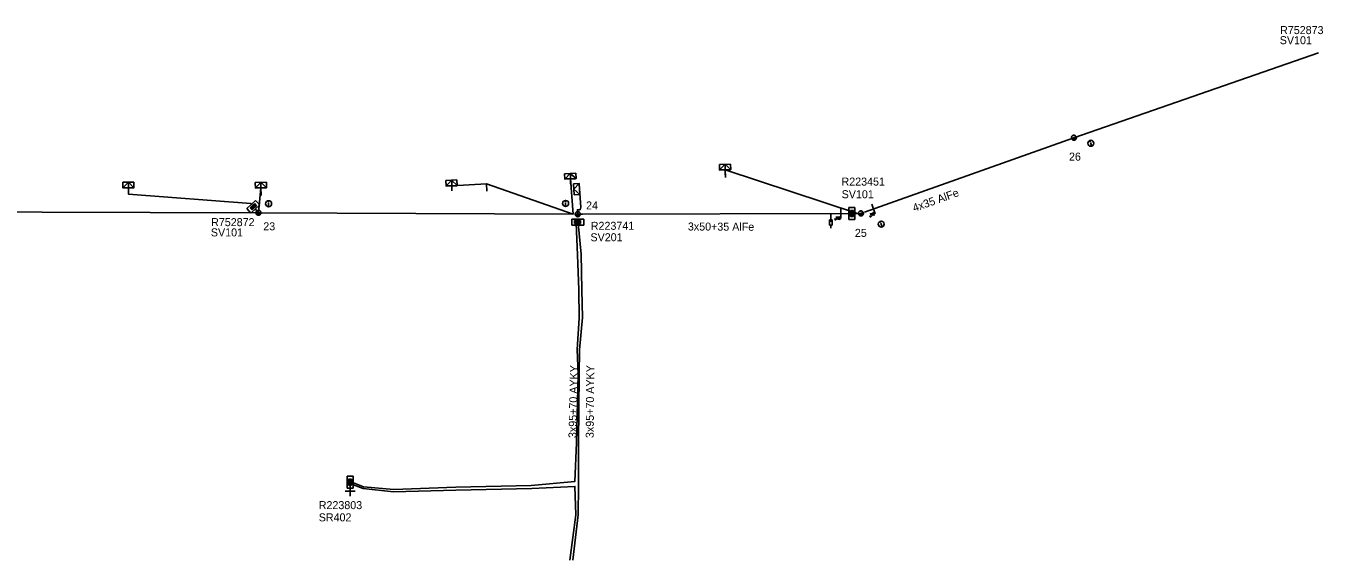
# Model space of a CAD drawing. Extents: x -544780 to -541582, y -1198995 to -1196551.
# Drawn here: x -541744 to -541581.9, y -1198987 to -1198920.2 of the extents above; entities that cross this region are included whole.
import ezdxf

# ---------------------------------------------------------------- set-up
doc = ezdxf.new("R2010")
doc.units = 0
for name, color, linetype in [('Vrstva 1', 7, 'Continuous'), ('Vrstva 10', 7, 'Continuous'), ('Vrstva 13', 7, 'Continuous'), ('Vrstva 14', 7, 'Continuous'), ('Vrstva 15', 7, 'Continuous'), ('Vrstva 16', 7, 'Continuous'), ('Vrstva 18', 7, 'Continuous'), ('Vrstva 2', 7, 'Continuous'), ('Vrstva 28', 7, 'Continuous'), ('Vrstva 29', 7, 'Continuous'), ('Vrstva 30', 7, 'Continuous'), ('Vrstva 31', 7, 'Continuous'), ('Vrstva 34', 7, 'Continuous'), ('Vrstva 36', 7, 'Continuous'), ('Vrstva 5', 7, 'Continuous'), ('Vrstva 52', 7, 'Continuous'), ('Vrstva 54', 7, 'Continuous'), ('Vrstva 59', 7, 'Continuous'), ('Vrstva 6', 7, 'Continuous'), ('Vrstva 8', 7, 'Continuous'), ('Vrstva 9', 7, 'Continuous')]:
    doc.layers.add(name, color=color, linetype=linetype)

# ---------------------------------------------------------------- blocks, each defined once
blk = doc.blocks.new('NN440')
at = {"layer": 'Vrstva 2'}
for points in [[(0.63, 0), (0.63, 0.06), (0.62, 0.13), (0.6, 0.19), (0.58, 0.25), (0.55, 0.31), (0.51, 0.37), (0.47, 0.42), (0.42, 0.46), (0.37, 0.51), (0.32, 0.54), (0.26, 0.57), (0.2, 0.59), (0.13, 0.61), (0.07, 0.62), (0, 0.63), (-0.06, 0.62), (-0.13, 0.61), (-0.19, 0.59), (-0.26, 0.57), (-0.31, 0.54), (-0.37, 0.51), (-0.42, 0.46), (-0.47, 0.42), (-0.51, 0.37), (-0.54, 0.31), (-0.57, 0.25), (-0.6, 0.19), (-0.62, 0.13), (-0.63, 0.06), (-0.63, 0), (-0.63, -0.07), (-0.62, -0.14), (-0.6, -0.2), (-0.57, -0.26), (-0.54, -0.32), (-0.51, -0.37), (-0.47, -0.43), (-0.42, -0.47), (-0.37, -0.51), (-0.31, -0.55), (-0.26, -0.58), (-0.19, -0.6), (-0.13, -0.62), (-0.06, -0.63), (0, -0.63), (0.07, -0.63), (0.13, -0.62), (0.2, -0.6), (0.26, -0.58), (0.32, -0.55), (0.37, -0.51), (0.42, -0.47), (0.47, -0.43), (0.51, -0.37), (0.55, -0.32), (0.58, -0.26), (0.6, -0.2), (0.62, -0.14), (0.63, -0.07), (0.63, 0)], [(-0.63, 0), (0.63, 0)], [(-0.6, -0.18), (0.57, -0.18)], [(-0.51, -0.32), (0.5, -0.32)], [(-0.37, -0.47), (0.35, -0.47)]]:
    blk.add_lwpolyline(points, dxfattribs=at)
blk = doc.blocks.new('NN840')
at = {"layer": 'Vrstva 15'}
for points in [[(0, 0.62), (0, -0.63)], [(-0.75, -0.71), (-0.75, -0.66)], [(-0.73, -0.76), (-0.75, -0.71)], [(-0.66, -0.8), (-0.73, -0.76)], [(-0.63, -0.8), (-0.66, -0.8)], [(-0.56, -0.76), (-0.63, -0.8)], [(-0.54, -0.71), (-0.56, -0.76)], [(-0.54, -0.38), (-0.54, -0.71)], [(-0.33, -0.38), (-0.33, -0.8)], [(-0.33, -0.64), (-0.13, -0.38)], [(-0.26, -0.56), (-0.09, -0.8)]]:
    blk.add_lwpolyline(points, dxfattribs=at)
blk = doc.blocks.new('NN770')
at = {"layer": 'Vrstva 10'}
for p, q in [((0, 0.19), (0, 0.26)), ((0, -0.28), (0, 0.11))]:
    blk.add_line(p, q, dxfattribs=at)
blk.add_circle((0, -0.01), 0.375, dxfattribs=at)
blk = doc.blocks.new('NN800')
at = {"layer": 'Vrstva 1'}
for points in [[(-0.44, 0.44), (0.44, -0.44)], [(-0.44, -0.44), (0.44, 0.44)]]:
    blk.add_lwpolyline(points, dxfattribs=at)
blk = doc.blocks.new('NN820')
at = {"layer": 'Vrstva 13'}
for points in [[(0, 0), (0, -1.05)], [(-0.16, -0.81), (0.16, -0.81)], [(-0.16, -1.47), (-0.16, -0.81)], [(0.16, -1.47), (-0.16, -1.47)], [(0, -1.05), (-0.06, -0.93)], [(0, -1.05), (0.06, -0.93)], [(0, -1.47), (0, -1.87)], [(0.16, -0.81), (0.16, -1.47)]]:
    blk.add_lwpolyline(points, dxfattribs=at)
blk = doc.blocks.new('NN620')
at = {"layer": 'Vrstva 8'}
for points in [[(0.75, 0), (-0.75, 0)], [(-0.75, 0), (-0.75, -0.75)], [(0.75, -0.75), (0.75, 0)], [(-0.75, -0.75), (0.75, -0.75)], [(0.37, -0.18), (-0.38, -0.18)], [(-0.38, -0.18), (-0.38, -0.56)], [(-0.38, -0.56), (0.37, -0.56)], [(0.32, -0.23), (-0.33, -0.23)], [(-0.33, -0.23), (-0.33, -0.51)], [(-0.33, -0.51), (0.32, -0.51)], [(0.27, -0.27), (-0.28, -0.27)], [(-0.28, -0.27), (-0.28, -0.46)], [(-0.28, -0.46), (0.27, -0.46)], [(0.23, -0.32), (-0.23, -0.32)], [(-0.23, -0.32), (-0.23, -0.42)], [(-0.23, -0.42), (0.23, -0.42)], [(-0.19, -0.37), (0.19, -0.37)], [(0.23, -0.42), (0.23, -0.32)], [(0.27, -0.46), (0.27, -0.27)], [(0.32, -0.51), (0.32, -0.23)], [(0.37, -0.56), (0.37, -0.18)]]:
    blk.add_lwpolyline(points, dxfattribs=at)
blk = doc.blocks.new('NN630')
at = {"layer": 'Vrstva 9'}
for points in [[(0, -0.7), (-0.7, 0)], [(-0.7, -0.7), (-0.7, 0), (0.7, 0), (0.7, -0.7)], [(-0.7, -0.7), (0.7, -0.7)], [(0, -0.7), (0.7, 0)]]:
    blk.add_lwpolyline(points, dxfattribs=at)
blk = doc.blocks.new('NN510')
at = {"layer": 'Vrstva 2'}
blk.add_lwpolyline([(0, 0), (0, 0.94)], dxfattribs=at)

msp = doc.modelspace()

# ---------------------------------------------------------------- linework, layer by layer
at = {"layer": 'Vrstva 1'}
for points in [[(-541639.19, -1198943.5), (-541613.01, -1198934.2), (-541582.42, -1198923.58)], [(-541755.51, -1198943.46), (-541714.92, -1198943.58)], [(-541714.92, -1198943.58), (-541675.59, -1198943.75)], [(-541640.07, -1198943.66), (-541674.42, -1198943.75)]]:
    msp.add_lwpolyline(points, dxfattribs=at)
at = {"layer": 'Vrstva 5'}
for points in [[(-541714.92, -1198943.58), (-541715.31, -1198943.1)], [(-541703.15, -1198977.33), (-541703.02, -1198977.33), (-541701.78, -1198977.83), (-541698.01, -1198978.16), (-541690.26, -1198977.87), (-541680.85, -1198977.66), (-541675.38, -1198977.17), (-541675.17, -1198972.31), (-541674.97, -1198963.79), (-541675.07, -1198960.68), (-541674.85, -1198956.74), (-541674.86, -1198953.22), (-541675.06, -1198948.85), (-541675.19, -1198944.91)], [(-541675.62, -1198986.97), (-541674.96, -1198981.34), (-541674.93, -1198977.66), (-541674.91, -1198972.28), (-541674.84, -1198963.81), (-541674.79, -1198960.69), (-541674.41, -1198956.68), (-541674.5, -1198953.2), (-541674.57, -1198948.77), (-541674.98, -1198944.89)], [(-541676, -1198986.97), (-541675.25, -1198981.34), (-541675.37, -1198977.78), (-541680.75, -1198978.03), (-541690.24, -1198978.22), (-541698.02, -1198978.45), (-541701.81, -1198978.05), (-541703.02, -1198977.58), (-541703.13, -1198977.58)]]:
    msp.add_lwpolyline(points, dxfattribs=at)
at = {"layer": 'Vrstva 52'}
for points in [[(-541715.74, -1198942.59), (-541715.88, -1198942.42), (-541731.17, -1198941.24), (-541731.17, -1198940.45)], [(-541674.42, -1198943.75), (-541675.01, -1198943.75), (-541675.05, -1198943.2), (-541674.72, -1198943.2), (-541674.62, -1198942.86), (-541674.81, -1198940.6)]]:
    msp.add_lwpolyline(points, dxfattribs=at)
at = {"layer": 'Vrstva 54'}
for points in [[(-541640.07, -1198943.66), (-541656.58, -1198938.22)], [(-541714.92, -1198943.58), (-541714.6, -1198940.47)], [(-541675.59, -1198943.75), (-541675.92, -1198939.35)]]:
    msp.add_lwpolyline(points, dxfattribs=at)
at = {"layer": 'Vrstva 59'}
msp.add_lwpolyline([(-541703.45, -1198977.9), (-541703.45, -1198978.35)], dxfattribs=at)
at = {"layer": 'Vrstva 8'}
msp.add_lwpolyline([(-541675.59, -1198943.75), (-541686.42, -1198939.94), (-541690.76, -1198940.2)], dxfattribs=at)

# ---------------------------------------------------------------- block references
at = {"layer": 'Vrstva 13'}
for p, xscale, yscale, rotation in [((-541613.01, -1198934.2), 0.5, 0.5, 19.570577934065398), ((-541714.92, -1198943.58), 0.49999999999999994, 0.49999999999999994, 0.11502770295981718), ((-541675.01, -1198943.75), 0.5, 0.5, 0.11513889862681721), ((-541639.62, -1198943.66), 0.5, 0.5, 19.570577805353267)]:
    msp.add_blockref('NN440', p, dxfattribs=dict(at, xscale=xscale, yscale=yscale, rotation=rotation))
for p, rotation in [((-541656.58, -1198938.22), -177.143300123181), ((-541714.6, -1198940.47), -178.132975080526), ((-541686.42, -1198939.94), -176.52494994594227), ((-541675.91, -1198939.35), -176.4414111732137)]:
    msp.add_blockref('NN510', p, dxfattribs=dict(at, rotation=rotation))
at = {"layer": 'Vrstva 16', "rotation": -0.25828065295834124}
msp.add_blockref('NN820', (-541643.37, -1198943.64), dxfattribs=at)
at = {"layer": 'Vrstva 18'}
for p, rotation in [((-541642.14, -1198943.65), -0.25834444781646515), ((-541638.06, -1198943.1), 19.56919731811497)]:
    msp.add_blockref('NN840', p, dxfattribs=dict(at, rotation=rotation))
at = {"layer": 'Vrstva 28'}
for p, rotation in [((-541715.31, -1198943.1), -136.96449832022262), ((-541640.37, -1198943.66), -90.257999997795), ((-541675.02, -1198944.37), 0.1150001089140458), ((-541703.09, -1198977.23), -89.49306671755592)]:
    msp.add_blockref('NN620', p, dxfattribs=dict(at, rotation=rotation))
at = {"layer": 'Vrstva 31'}
for p, rotation in [((-541656.58, -1198938.22), -177.14329998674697), ((-541675.91, -1198939.35), -176.44141116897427), ((-541731.17, -1198940.45), 179.8937971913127), ((-541714.6, -1198940.47), -178.13297494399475), ((-541690.76, -1198940.2), -176.52494994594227), ((-541674.81, -1198940.6), -86.42367349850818)]:
    msp.add_blockref('NN630', p, dxfattribs=dict(at, rotation=rotation))
at = {"layer": 'Vrstva 34', "rotation": 45}
for p in [(-541656.58, -1198938.22), (-541675.92, -1198939.35), (-541731.17, -1198940.45), (-541714.6, -1198940.47), (-541690.76, -1198940.2), (-541703.45, -1198978.35)]:
    msp.add_blockref('NN800', p, dxfattribs=at)
at = {"layer": 'Vrstva 36'}
for p, rotation in [((-541610.9, -1198934.89), 19.147274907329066), ((-541713.64, -1198942.44), 0.11502783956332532), ((-541676.53, -1198942.4), -0.25828051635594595), ((-541637.09, -1198944.99), 19.56919716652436)]:
    msp.add_blockref('NN770', p, dxfattribs=dict(at, rotation=rotation))

# ---------------------------------------------------------------- texts
at = {"layer": 'Vrstva 14'}
for s, p in [('26', (-541613.62, -1198937.06)), ('24', (-541673.97, -1198943.16)), ('23', (-541714.31, -1198945.77)), ('25', (-541640.38, -1198946.59))]:
    msp.add_text(s, height=1, dxfattribs=at).set_placement(p)
at = {"layer": 'Vrstva 2'}
for s, rotation, p in [('4x35 AlFe', 19.569, (-541632.96, -1198943.48)), ('3x50+35 AlFe', 359.742, (-541661.25, -1198945.79))]:
    msp.add_text(s, height=1, rotation=rotation, dxfattribs=at).set_placement(p)
at = {"layer": 'Vrstva 29'}
for s, p in [('R752873', (-541587.24, -1198921.25)), ('R223451', (-541642.05, -1198940.18)), ('R752872', (-541720.83, -1198945.25)), ('R223803', (-541707.38, -1198980.61))]:
    msp.add_text(s, height=1, dxfattribs=at).set_placement(p)
msp.add_text('R223741', height=1, rotation=0.115, dxfattribs=at).set_placement((-541673.38, -1198945.71))
at = {"layer": 'Vrstva 30'}
for s, p in [('SV101', (-541587.28, -1198922.51)), ('SV101', (-541642.03, -1198941.76)), ('SV101', (-541720.86, -1198946.53)), ('SR402', (-541707.38, -1198982.14))]:
    msp.add_text(s, height=1, dxfattribs=at).set_placement(p)
msp.add_text('SV201', height=1, rotation=0.115, dxfattribs=at).set_placement((-541673.42, -1198947.14))
at = {"layer": 'Vrstva 6'}
for rotation, p in [(88.655, (-541675.18, -1198971.74)), (89.526, (-541673.02, -1198971.73))]:
    msp.add_text('3x95+70 AYKY', height=1, rotation=rotation, dxfattribs=at).set_placement(p)

doc.saveas('drawing.dxf')
